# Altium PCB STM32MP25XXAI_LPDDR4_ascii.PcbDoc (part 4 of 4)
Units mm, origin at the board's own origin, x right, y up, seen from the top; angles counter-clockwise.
Board outline 172 x 137 mm, 4 copper layers (Top Layer, Signal Layer 1, Signal Layer 2, Bottom Layer), stack 1.614 mm thick; 188 components, 144 nets, 1216 pads, 838 vias.
Unrouted connection lines stored in the file: 13.
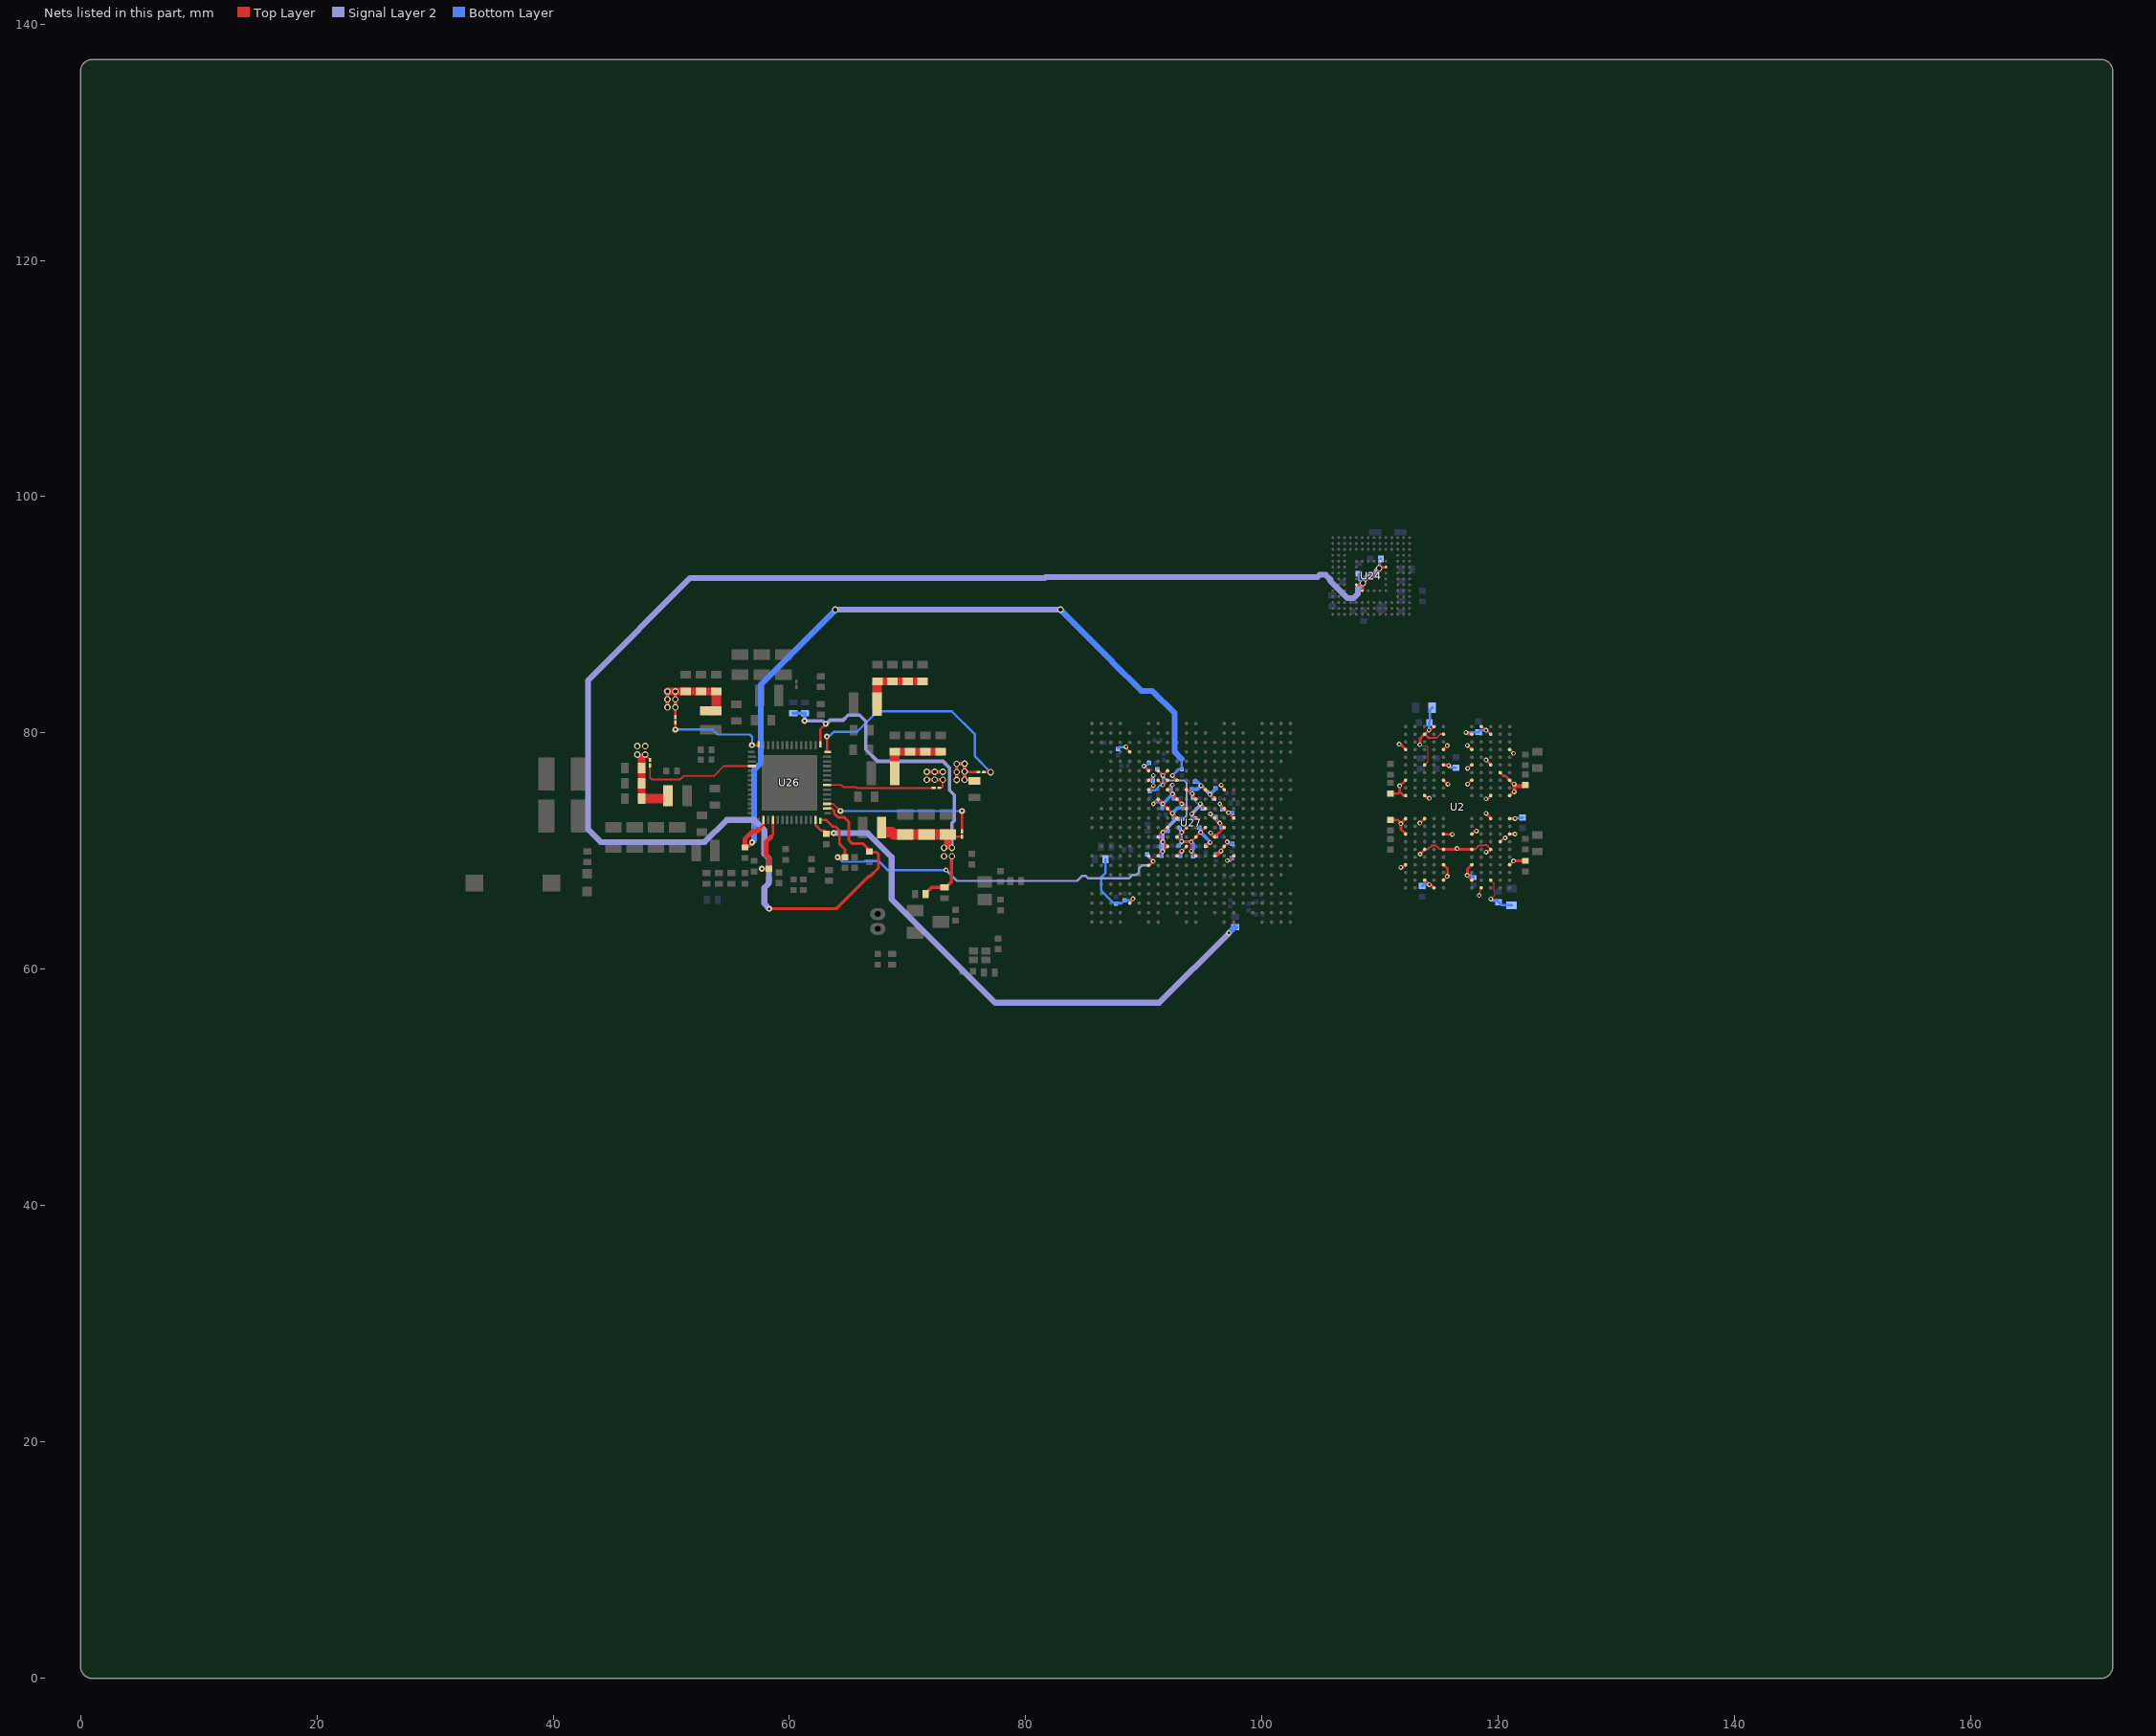
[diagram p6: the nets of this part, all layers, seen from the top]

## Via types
v1: diameter 0.55, hole 0.35, Top Layer to Bottom Layer, 387 vias
v2: diameter 0.4, hole 0.2, Top Layer to Bottom Layer, tented both sides, 173 vias
v3: diameter 0.5, hole 0.2, Top Layer to Bottom Layer, 146 vias
v4: diameter 0.4, hole 0.2, Top Layer to Bottom Layer, 129 vias
v5: diameter 0.5, hole 0.25, Top Layer to Bottom Layer, 3 vias

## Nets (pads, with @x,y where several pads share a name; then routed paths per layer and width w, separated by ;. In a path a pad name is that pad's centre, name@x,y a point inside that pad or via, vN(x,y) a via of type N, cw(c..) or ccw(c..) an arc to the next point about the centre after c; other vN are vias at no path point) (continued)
VDD2_DDR: C41.2 C50.1 C53.2 C54.1 C55.2 C56.2 C57.2 C58.2 C59.2 C60.2 C105.2 C106.1 C107.1 C108.1 C123.2 C124.1 C125.1 C130.1 C151.1 C175.1 C176.2 C200.2 C202.2 L5.2 LNK8.2 R163.2 U2.A4 U2.A9 U2.AA3 U2.AA5 U2.AA8 U2.AA10 U2.AB4 U2.AB9 U2.B3 U2.B5 U2.B8 U2.B10 U2.D1 U2.D5 U2.D8 U2.D12 U2.F3 U2.F5 U2.F8 U2.F10 U2.G2 U2.H1 U2.H5 U2.H8 U2.H12 U2.K1 U2.K3 U2.K10 U2.K12 U2.N1 U2.N3 U2.N10 U2.N12 U2.R1 U2.R5 U2.R8 U2.R12 U2.T2 U2.U3 U2.U5 U2.U8 U2.U10 U2.W1 U2.W5 U2.W8 U2.W12 U27.K15 U27.L14 U27.L16 U27.M15 U27.N14 U27.P15 U27.R14 U27.R16 | length 71.9
  Top Layer w0.09: v4(113.35,79) 113.413,78.938 113.905,78.938 114.045,78.797 114.045,77.595 U2.U10@113.75,77.3 ; v4(118.375,66.25) 118.397,66.271 118.397,66.524 118.515,66.642 118.515,66.865 U2.A4@118.55,66.9 ; v4(119.35,65.95) 119.695,66.295 119.695,66.593 119.645,66.643 119.645,67.255 U2.B3@119.35,67.55 ; U2.K3@119.35,72.775 U2.K3@119.35,72.788 ; U2.K1@120.95,72.825 U2.K1@120.975,72.825
  Top Layer w0.1: U27.R16@97.575,69.6 U27.R16@97.6,69.6
  Top Layer w0.15: v1(47.798,78.165) 48.2,77.763 LNK8.2@48.2,77.723 ; U2.F10@113.75,70.15 113.76,70.16 114.035,70.16 114.35,70.475 114.732,70.475 115.032,70.175 U2.F8@115.35,70.175 ; 114.095,79.575 114.75,79.575 115.075,79.9 U2.AA8@115.35,79.9 ; U2.F8@115.35,70.15 U2.F8@115.367,70.166 ; U2.F5@117.75,70.15 118.025,70.15 118.35,70.475 118.685,70.475 118.712,70.502 118.903,70.502 118.95,70.55 ; 118.95,70.525 118.975,70.525 119.325,70.175 U2.F3@119.375,70.175
  Top Layer w0.2: v2@95.6,73.15 v2(95.625,73.15) 95.65,73.15 U27.L14@96,72.8 v2(96.42,72.379) ; v2@95.625,71.575 U27.N14@96,71.2 U27.M15@96.8,72 v2@96.421,72.379 ; v2@96.4,74 U27.K15@96.8,73.6 v2(97.15,73.25) ; v2(96.525,70) 96.563,70.038 96.563,70.163 U27.P15@96.8,70.4 97.05,70.65 v2(97.05,70.8) ; v2(97.05,69.2) 97.2,69.2 U27.R16@97.6,69.6 ; v2@97.125,73.275 v2(97.15,73.25) ; U27.L16@97.6,72.8 v2(97.15,73.25)
  Top Layer w0.22: C50.1@110.85,72.65 111.46,72.65 111.735,72.375 v4@111.75,72.375 ; C105.2@110.85,74.875 111.502,74.875 111.651,75.024 ; v4(111.6,79.05) 111.635,79.016 111.735,79.016 U2.W12@112.15,78.6 ; v4(111.75,68.625) 111.785,68.659 111.938,68.659 112.129,68.85 U2.D12@112.15,68.85 ; U2.H12@112.15,71.45 111.755,71.845 111.755,72.37 v4@111.75,72.375 ; U2.K12@112.15,72.75 112.138,72.75 111.763,72.375 v4@111.75,72.375 ; U2.N12@112.15,74.7 112.135,74.715 111.96,74.715 111.651,75.024 ; U2.R12@112.15,76 112.15,75.988 111.65,75.488 111.65,75.475 111.651,75.474 111.651,75.024 ; v4(113.35,72.375) 113.363,72.375 113.738,72.75 U2.K10@113.75,72.75 ; v4(113.35,79) 113.38,79.03 113.38,79.53 U2.AA10@113.75,79.9 U2.AA10@113.77,79.9 ; v4(113.375,69.75) 113.75,70.125 U2.F10@113.75,70.15 ; U2.B10@113.75,67.55 113.763,67.55 114.138,67.175 v4(114.15,67.175) 114.185,67.141 114.288,67.141 114.529,66.9 U2.A9@114.55,66.9 ; U2.N10@113.75,74.7 113.772,74.7 113.953,74.519 114.116,74.519 v4@114.15,74.485 ; 114.095,79.575 U2.AA10@113.77,79.9 ; U2.AB9@114.55,80.55 114.538,80.55 114.188,80.2 114.175,80.2 114.141,80.166 114.038,80.166 113.772,79.9 U2.AA10@113.77,79.9 ; U2.B8@115.35,67.55 v4(115.675,67.875) 115.675,67.924 115.71,67.959 115.71,68.49 U2.D8@115.35,68.85 ; U2.F8@115.35,70.175 115.363,70.163 116.413,70.163 116.425,70.175 116.438,70.163 117.738,70.163 U2.F5@117.75,70.15 ; U2.H8@115.35,71.45 115.363,71.438 116.088,71.438 v4(116.1,71.425) ; U2.R8@115.35,76 115.372,76 115.697,75.675 v4(115.725,75.675) ; U2.U8@115.35,77.3 115.366,77.285 115.717,77.285 115.752,77.25 v4(115.8,77.25) ; U2.W8@115.35,78.6 v4(115.675,78.925) ; v4(117.25,80.05) 117.299,80.05 117.434,79.915 117.735,79.915 U2.AA5@117.75,79.9 ; v4(117.375,78.95) 117.388,78.95 117.738,78.6 U2.W5@117.75,78.6 ; v4(117.4,75.675) U2.R5@117.713,75.988 ; v4(117.4,77) 117.425,77 U2.U5@117.741,77.315 ; U2.B5@117.75,67.55 v4(117.35,67.95) 117.38,67.98 117.38,68.48 U2.D5@117.75,68.85 ; U2.H5@117.75,71.45 117.772,71.45 118.038,71.716 118.116,71.716 v4@118.15,71.75 ; U2.AB4@118.55,80.55 118.572,80.55 118.863,80.259 118.916,80.259 v4(118.95,80.225) 118.985,80.191 119.038,80.191 119.329,79.9 U2.AA3@119.35,79.9 ; v4(118.95,69.925) 118.985,69.959 119.138,69.959 119.329,70.15 U2.F3@119.35,70.15 ; v4(118.95,73.2) 118.95,73.172 119.35,72.772 U2.K3@119.35,72.75 ; v4(118.95,74.425) 118.985,74.459 119.11,74.459 U2.N3@119.35,74.7 ; v4(118.95,77.725) 118.95,77.713 119.35,77.313 U2.U3@119.35,77.3 ; U2.T2@120.123,76.655 120.145,76.655 U2.T2@120.15,76.65 120.425,76.375 120.575,76.375 U2.R1@120.95,76 121.241,75.709 121.316,75.709 v4(121.35,75.675) ; U2.G2@120.15,70.8 120.172,70.8 120.463,71.091 120.541,71.091 v4(120.575,71.125) ; U2.D1@120.95,68.85 v4(121.275,69.175) C106.1@122.25,69.175 ; U2.H1@120.95,71.45 v4(121.4,71.45) ; U2.K1@120.95,72.763 U2.K1@120.95,72.75 v4(121.4,72.75) ; U2.N1@120.95,74.7 121.241,74.991 121.316,74.991 v4(121.35,75.025) ; U2.W1@120.95,78.6 120.963,78.6 121.263,78.3 v4@121.275,78.3
  Top Layer w0.3: U27.R14@96,69.6 96.125,69.6 v2(96.525,70) ; v4(121.35,75.025) v4@121.35,75.495 ; v4(121.35,75.675) v4@121.35,75.495 ; C107.1@122.275,75.6 122.17,75.495 v4@121.35,75.495
  Top Layer w0.64: C202.2@47.475,74.45 C41.2@47.475,75.75 C200.2@47.475,77.05 ; 47.475,77.495 47.475,77.925
  Top Layer w0.8: C202.2@47.7,74.45 L5.2@49.475,74.45
  Signal Layer 2 w0.3: v2@96.356,72.394 96.406,72.394 v2@96.425,72.375
  Bottom Layer w0.2: v2@96.4,74 96.4,73.946 96.549,73.796 96.549,73.599 C60.2@96.624,73.524 ; C60.2@96.631,73.524 96.704,73.452 96.933,73.452 97.135,73.25 v2(97.15,73.25) ; v2@97.125,73.275 v2(97.15,73.25) ; v2@97.15,73.23 v2(97.15,73.25)
  Bottom Layer w0.22: v4(114.125,80.25) 114.125,80.825 114.202,80.901 114.202,81.926 C123.2@114.4,82.125 ; v4@114.125,80.275 114.125,80.85 C125.1@114.175,80.9 114.202,80.926 114.202,81.951 C123.2@114.4,82.15 ; v4@115.8,77.275 116.022,77.054 116.397,77.054 C130.1@116.4,77.05 ; v4(117.25,80.05) 118.275,80.05 C124.1@118.3,80.075 118.441,80.216 118.916,80.216 v4@118.95,80.25 ; v4@117.35,67.975 117.675,67.975 R163.2@117.9,67.75 ; v4@119.35,65.975 119.399,65.975 119.554,65.82 119.88,65.82 C108.1@120.025,65.675 120.05,65.675 120.3,65.425 C176.2@121.125,65.425 ; v4@121.4,72.775 121.435,72.809 122.01,72.809 C151.1@122.05,72.85
  Bottom Layer w0.275: C175.1@113.55,67.05 113.7,67.2 v4@114.15,67.2
  Bottom Layer w0.3: v2@95.6,71.575 95.9,71.275 C55.2@96.1,71.275 ; v2@95.6,73.15 v2(95.625,73.15) ; v2@95.627,73.15 v2(95.625,73.15) ; C59.2@96.1,69.725 96.175,69.8 96.308,69.8 96.508,70 v2(96.525,70) ; v2(96.42,72.379) 96.394,72.379 96.124,72.649 96.124,72.687 96.099,72.712 96.099,72.85 C56.2@96.074,72.875 96.049,72.9 95.875,72.9 v2(95.625,73.15) ; v2@96.425,72.375 96.425,72.347 96.549,72.223 96.549,71.999 C57.2@96.574,71.974 ; v2@97.023,70.8 v2(97.05,70.8) 97.077,70.8 97.227,70.65 97.45,70.65 C54.1@97.475,70.625 ; v2(97.05,69.2) 97.069,69.219 97.269,69.219 C53.2@97.45,69.4 ; v2@97.125,73.275 97.425,73.275 C58.2@97.5,73.2
  other v1: 47.123,78.165 47.123,78.89 47.798,78.89
  other v2: 95.65,71.55 96.425,74
  other v4: 116.5,70.225 118.15,71.7 111.75,72.325 114.15,74.475 111.65,75.525 121.275,78.275
VDD3V3_USB: C156.2 R286.1 U26.13 | length 47
  Top Layer w0.21: U26.13@62.2,72.63 62.2,72.2 62.663,71.737 62.918,71.737 62.92,71.735 62.99,71.735 63.125,71.6 C156.2@63.125,71.53
  Top Layer w0.3: C156.2@63.125,71.53 v3(63.735,71.53)
  Signal Layer 2 w0.5: v3(63.735,71.53) 66.62,71.53 68.65,69.5 68.65,65.93 77.411,57.17 91.295,57.17 97.19,63.065 v2(97.19,63.078)
  Bottom Layer w0.5: v2(97.19,63.078) 97.687,63.575 R286.1@97.725,63.575
VDD_DDR_FB: LNK8.1 U26.46 | length 10.2
  Top Layer w0.15: LNK8.1@48.2,77.273 48.2,76.19 48.317,76.073 50.767,76.073 51.067,76.373 51.737,76.373 51.739,76.375 53.627,76.375 54.452,77.2 U26.46@56.83,77.2
VDD_EMMC: C177.2 C180.2 C190.1 U24.E6 U24.F5 U24.J10 U24.K9 U26.16 | length 132.1
  Top Layer w0.2: U24.E6@107.98,92.542 108.285,92.542 108.435,92.692 v1(108.53,92.692) 108.53,92.1 108.48,92.05 U24.F5@108.48,92.042 ; v1(109.905,93.942) v1@109.98,94.017 ; U24.J10@109.98,94.542 109.98,94.112 109.972,94.104 109.972,94.025 v1@109.98,94.017 ; U24.K9@110.48,94.042 110.1,94.042 110.067,94.009 109.988,94.009 v1@109.98,94.017
  Top Layer w0.21: U26.16@63.17,73.6 63.6,73.6 63.788,73.412 63.788,73.188 63.934,73.041
  Top Layer w0.25: v3(58.3,65.125) 63.96,65.125 66.7,67.865 66.822,67.865 67.535,68.578 67.535,69.764 67.389,69.91 66.805,69.91 C190.1@66.75,69.965 ; 63.932,73.038 64.098,72.872 64.628,72.872 65.025,72.475 65.025,70.925 65.3,70.65 66.195,70.65 C190.1@66.75,70.095
  Top Layer w0.5: v1(108.53,92.692) v1@108.53,92.706 ; v1@109.895,93.919 v1@109.895,93.932
  Signal Layer 2 w0.5: v3(58.3,65.125) 57.872,65.553 57.872,66.908 58.265,67.301 58.265,69.369 57.872,69.762 57.872,71.786 57.009,72.649 54.703,72.649 52.827,70.773 44.024,70.773 42.958,71.839 42.958,84.457 51.616,93.115 81.606,93.115 81.691,93.2 104.684,93.2 104.871,93.387 105.389,93.387 105.755,93.021 105.755,92.873 107.221,91.407 107.739,91.407 108.105,91.773 108.105,92.254 108.53,92.679 v1(108.53,92.692) ; v1@108.605,92.946 108.986,93.327 109.374,93.327 109.755,93.708 109.755,93.779 v1@109.895,93.919
  Bottom Layer w0.2: C177.2@108.19,93.455 108.19,92.949 108.459,92.68 v1@108.55,92.68 ; v1@109.925,93.93 109.925,94.614 C180.2@110.05,94.739
VDD_SDCARD: C142.1 U26.4 | length 5.1
  Top Layer w0.21: 58.425,71.2 58.6,71.375 U26.4@58.6,72.63
  Top Layer w0.3: v3(57.665,68.51) C142.1@58.275,68.51
  Top Layer w0.4: C142.1@58.275,68.51 58.275,69.393 58.01,69.658 58.01,70.785 58.425,71.2
VDDA1V8_AON: C189.2 C234.2 U26.14 U27.R7 U27.T7 | length 35.8
  Top Layer w0.2: U27.T7@90.4,68.8 90.687,69.087 90.757,69.087 v2(90.795,69.125) 90.795,69.178 90.4,69.573 U27.R7@90.4,69.6
  Top Layer w0.21: U26.14@62.6,72.63 63.11,72.63 63.648,72.092 63.887,72.092 64.245,71.734 64.245,70.602 64.7,70.147 C189.2@64.7,69.49
  Top Layer w0.3: v3(64.09,69.49) C189.2@64.7,69.49
  Signal Layer 2 w0.2: v2(73.253,68.406) 73.259,68.406 74.183,67.482 84.342,67.482 84.76,67.9 85.091,67.9 85.292,67.699 88.734,67.699 89.034,68 89.2,68 89.366,68 89.6,68.234 89.6,68.566 89.835,68.8 90.47,68.8 v2(90.795,69.125) v2@90.726,69.125
  Bottom Layer w0.2: v3(64.09,69.49) 64.48,69.1 66.321,69.1 66.392,69.171 67.535,69.171 68.3,68.406 v2(73.253,68.406) ; C234.2@90.275,69.735 90.441,69.569 90.441,69.443 90.76,69.125 v2(90.795,69.125)
VDDCORE: C1.1 C2.2 C3.2 C4.1 C5.2 C6.2 C22.2 C23.2 C24.2 C66.2 C69.2 C70.2 C183.2 L2.2 LNK2.2 R249.1 U27.D5 U27.F7 U27.G7 U27.H7 U27.H9 U27.J8 U27.J10 U27.K9 U27.K11 U27.L10 | length 26.2
  Top Layer w0.2: C22.2@71.275,84.375 C22.2@71.323,84.423 ; v1@74.87,76.685 LNK2.2@75.98,76.685 ; v2(88.475,78.825) 88.475,78.725 U27.D5@88.8,78.4 ; v2(90,77.2) U27.F7@90.4,76.8 U27.F7@90.425,76.8 ; U27.H7@90.4,75.2 90.425,75.2 90.775,75.55 v2(90.8,75.55) ; U27.G7@90.4,76 v2(90.8,76.4) ; v2(90.8,74) U27.J8@91.2,74.4 v2(91.6,74) v2(92.4,73.2) U27.L10@92.8,72.8 ; v2(92.4,75.6) U27.H9@92,75.2 v2@92.425,74.775 ; v2(92.425,74.85) v2@92.425,74.775 ; U27.K11@93.6,73.6 v2(93.2,74) U27.J10@92.8,74.4 v2@92.425,74.775
  Top Layer w0.3: v1@74.151,77.404 v1(74.826,77.404) v1(74.826,76.729) ; v1(74.156,76.024) v1(74.156,76.699) v1(74.156,77.374) ; v1(74.826,76.054) v1(74.826,76.729) ; v1@74.87,76.685 v1(74.826,76.729)
  Top Layer w0.64: C183.2@67.45,84.375 C24.2@68.725,84.375 C23.2@70,84.375 C22.2@71.275,84.375
  Top Layer w0.8: L2.2@67.415,82.2 L2.2@67.415,82.45 C183.2@67.415,84.173
  Bottom Layer w0.2: C70.2@87.8,78.7 87.9,78.8 88.038,78.8 v2@88.4,78.8 ; v2(90,77.2) 90.038,77.238 90.188,77.238 C66.2@90.425,77.475 ; v2(90.8,75.55) 90.777,75.572 90.777,75.948 C69.2@90.755,75.97 90.777,75.992 90.777,76.378 v2(90.8,76.4)
  Bottom Layer w0.3: v2(90.8,74) 91,74.2 91.4,74.2 v2(91.6,74) ; C3.2@91.55,73.65 91.55,73.95 v2(91.6,74) ; v2(92.4,75.6) 92.275,75.475 C4.1@92.275,75.25 92.275,75 v2(92.425,74.85) ; C1.1@92.55,72.825 92.55,73.05 v2(92.4,73.2) 92.85,73.65 C2.2@93.326,73.65 93.325,73.875 v2(93.2,74) ; C5.2@92.551,74.475 92.55,74.725 v2(92.425,74.85) ; v2(91.6,74) 92.425,74.825 v2(92.425,74.85)
VDDCORE_FB: LNK2.1 U26.28 | length 19.9
  Top Layer w0.2: U26.28@63.17,78.4 v3(63.17,79.7) ; LNK2.1@76.444,76.687 v1@77.031,76.685
  Bottom Layer w0.2: v3(63.17,79.7) 63.227,79.757 63.401,79.757 63.754,80.111 65.734,80.111 67.457,81.833 73.744,81.833 75.675,79.902 75.675,78.041 v1(77.033,76.683)
VDDCPU: C13.1 C14.2 C15.2 C16.1 C17.2 C25.2 C26.2 C27.2 C28.2 C31.2 L3.2 LNK4.1 U27.H11 U27.H13 U27.H15 U27.J12 U27.J14 U27.K13 U27.L12 | length 21.1
  Top Layer w0.2: LNK4.1@50.35,81.35 v1(50.35,82.173) ; U27.H11@93.6,75.2 93.627,75.2 93.924,74.903 94.052,74.903 94.128,74.827 94.128,74.699 94.4,74.427 U27.J12@94.4,74.4 ; v2(94.045,73.155) U27.L12@94.4,72.8 ; v2(94.775,74.005) 95.18,73.6 U27.K13@95.2,73.6 ; v2(94.845,75.555) U27.H13@95.2,75.2 ; v2(95.595,74.805) U27.J14@96,74.4 ; v2(96.54,75.591) 96.578,75.553 96.578,75.449 96.8,75.227 U27.H15@96.8,75.2
  Top Layer w0.3: v1(49.675,82.173) v1(49.675,82.848) v1(49.675,83.523) v1(50.35,83.523) v1(50.35,82.848) v1(50.35,82.173)
  Top Layer w0.64: v1(49.675,83.523) 49.675,83.525 C27.2@51.2,83.525 C28.2@52.5,83.525 C26.2@53.8,83.525
  Top Layer w0.8: L3.2@53.35,81.875 53.8,81.875 53.8,83.173
  Signal Layer 2 w0.3: v2(94.045,73.155) 94.756,73.866 94.756,73.986 v2(94.775,74.005) ; v2(94.845,75.555) v2(95.595,74.805)
  Bottom Layer w0.1: C14.2@94.15,74.48 94.15,74.379 94.524,74.005 v2(94.775,74.005)
  Bottom Layer w0.2: v2(94.045,73.155) 94.045,72.855 C31.2@94.125,72.775 ; v2@94.775,73.978 v2(94.775,74.005) ; C13.1@94.95,73.625 94.95,73.803 ; v2(95.595,74.805) 95.633,74.767 95.633,74.692 C15.2@95.875,74.45
  Bottom Layer w0.3: v2(94.095,74.865) 94.095,74.892 94.05,74.937 94.05,75.225 C25.2@94.025,75.25 94.548,75.25 v2@94.853,75.555 ; C17.2@94.325,75.875 94.525,75.875 v2(94.845,75.555) ; v2@94.775,73.978 94.95,73.803 ; v2(95.595,74.805) C16.1@96.095,75.305
VDDCPU_FB: LNK4.2 U26.42 | length 8.6
  Top Layer w0.2: v3(50.35,80.29) LNK4.2@50.35,80.9 ; v3(56.825,78.975) U26.42@57.395,78.975
  Bottom Layer w0.2: v3@50.37,80.287 53.499,80.287 53.914,79.872 56.643,79.872 56.845,79.67 v3@56.845,78.972
VDDGPU: C7.2 C8.2 C9.2 C10.2 C11.1 C12.2 C34.2 C35.2 C36.2 C37.2 L4.2 LNK7.2 U27.M11 U27.M13 U27.N10 U27.N12 U27.P13 U27.R12 | length 21.3
  Top Layer w0.15: LNK7.2@72.675,75.35 72.682,75.358 72.885,75.358 72.973,75.445 v1(72.973,76.038)
  Top Layer w0.2: C35.2@73.05,78.393 C35.2@73.098,78.345 ; U27.M11@93.6,72 v2(93.2,71.6) U27.N10@92.8,71.2 93.197,70.803 93.997,70.803 v2(94,70.8) ; U27.R12@94.4,69.6 v2(94,70) v2(94,70.8) ; U27.P13@95.2,70.4 95.487,70.687 95.562,70.687 v2(95.6,70.725) ; U27.M13@95.2,72 v2(94.8,71.6) v2(94,70.8)
  Top Layer w0.3: v1(71.623,76.038) v1(72.298,76.038) v1(72.973,76.038) ; v1(71.623,76.713) v1(72.298,76.713) v1(72.973,76.713)
  Top Layer w0.64: C37.2@68.9,78.4 C36.2@70.2,78.4 C34.2@71.5,78.4 C35.2@72.8,78.4
  Top Layer w0.8: L4.2@68.925,76.6 68.925,78.073
  Bottom Layer w0.2: C9.2@93.025,72 93.025,71.775 v2(93.2,71.6) 93.197,71.598 93.197,70.808 93.195,70.805 93.197,70.803 93.997,70.803 v2(94,70.8) ; v2(95.6,70.725) v2@95.61,70.715
  Bottom Layer w0.3: C10.2@92.95,70.48 93.176,70.706 93.176,70.786 v2@93.195,70.805 ; v2(94,70.8) 94.175,70.625 94.175,70.175 v2(94,70) 94.2,69.8 C12.2@94.2,69.575 ; C7.2@94.675,72 94.8,71.875 v2(94.8,71.6) 94.833,71.567 95.581,70.819 95.581,70.744 v2(95.6,70.725) 95.581,70.706 95.506,70.706 C11.1@95.25,70.45
  other v2: 93.2,70.805
VDDGPU_FB: LNK7.1 U26.21 | length 9.3
  Top Layer w0.15: U26.21@63.05,75.6 64.383,75.6 64.56,75.423 65.64,75.423 65.713,75.35 LNK7.1@72.225,75.35
VDDIO: C19.2 C44.1 C45.2 C46.2 C47.1 C52.2 C73.2 C74.2 C186.2 C187.2 L6.2 LNK11.2 R27.2 R67.2 R260.2 R261.2 U26.29 U27.F8 U27.F9 U27.G8 U27.G9 U27.M9 U27.N8 U27.P9 U27.P11 U27.R8 U27.R10 | length 61.4
  Top Layer w0.2: U26.29@62.6,79.045 62.6,80.298 v3(63.075,80.773) ; C186.2@73.4,71.4 73.585,71.215 LNK11.2@74.6,71.215 ; U27.R8@91.2,69.6 v2(91.575,69.975) U27.P9@92,70.4 v2(91.6,70.8) U27.N8@91.2,71.2 v2(91.6,71.6) U27.M9@92,72 ; U27.G8@91.2,76 91.599,75.6 U27.G9@92,76 ; U27.F8@91.2,76.8 v2(91.6,76.4) U27.F9@92,76.8 ; U27.R10@92.8,69.6 v2(93.2,70) U27.P11@93.6,70.4
  Top Layer w0.3: R67.2@71.525,66.375 71.525,66.44 72.01,66.925 R27.2@73.125,66.925 73.23,67.03 73.339,67.03 73.712,67.402 73.712,69.52 v1(73.752,69.56) ; v1(73.077,69.56) v1@73.125,69.512
  Top Layer w0.64: 73.4,70.525 C186.2@73.4,70.955
  Top Layer w0.9: L6.2@67.85,71.6 68.65,71.6 68.85,71.4 C187.2@69.8,71.4 C19.2@71.6,71.4 C186.2@73.4,71.4
  Signal Layer 2 w0.15: v2(91.599,75.599) 91.971,75.971 91.962,75.98 ; v2@91.6,76.338 v2@91.6,76.342 ; v2(91.6,76.4) v2@91.6,76.342 ; 93.301,72.703 93.608,73.01 93.608,75.783 93.411,75.98 91.962,75.98 ; v2@91.6,76.342 91.962,75.98
  Signal Layer 2 w0.3: v3(61.284,81.027) 62.799,81.027 63.05,80.776 v3@63.075,80.776 ; v3(63.075,80.773) 63.129,80.773 63.44,81.084 64.543,81.084 64.973,81.513 65.931,81.513 66.455,80.989 66.455,78.601 67.456,77.6 72.999,77.6 73.551,77.048 73.551,75.156 73.951,74.756 73.951,72.573 73.752,72.375 v1(73.752,70.285) ; v2(91.575,69.975) 91.6,70 v2(91.6,71.6) 92.703,72.703 93.301,72.703
  Bottom Layer w0.2: C74.2@90.5,75.05 90.575,75.125 90.667,75.125 90.692,75.15 90.931,75.15 90.946,75.165 90.981,75.165 91.2,75.384 91.2,75.419 91.342,75.561 91.561,75.561 v2(91.599,75.599) 91.6,76.4 91.6,76.45 C73.2@91.125,76.925
  Bottom Layer w0.3: R260.2@60.33,81.68 R261.2@61.305,81.68 61.294,81.669 61.294,81.038 v3(61.284,81.027) ; C44.1@91.475,69.6 91.475,69.875 v2(91.575,69.975) 91.475,70.075 91.475,70.675 v2(91.6,70.8) 91.475,70.925 91.475,71.475 91.725,71.725 C46.2@92.025,71.725 ; C45.2@93.075,69.6 93.075,69.875 v2(93.2,70) v2@93.225,70
  other v1: 73.077,70.285
VDDIO_FB: LNK11.1 U26.17 | length 13.4
  Top Layer w0.15: U26.17@63.17,74 63.7,74 64.303,73.397 v3(64.315,73.397)
  Top Layer w0.2: LNK11.1@74.6,71.665 v3(74.6,73.4)
  Bottom Layer w0.15: v3(64.315,73.397) v3@74.597,73.397
VDDIO_SDCARD: C71.2 C217.1 U26.2 U27.G10 | length 65.5
  Top Layer w0.2: v2(92.4,76.4) U27.G10@92.8,76
  Top Layer w0.21: 57.459,71.873 57.8,72.214 U26.2@57.8,72.63
  Top Layer w0.3: C217.1@56.225,70.38 56.27,70.425 56.559,70.425 56.835,70.701 v3(56.835,70.737)
  Top Layer w0.4: C217.1@56.225,70.32 56.225,70.38 56.225,71.015 56.899,71.69 57.275,71.69 57.459,71.873
  Signal Layer 2 w0.5: v1(63.865,90.43) 63.867,90.432 82.942,90.432 v1(82.945,90.435)
  Bottom Layer w0.2: v2(92.4,76.4) 92.95,76.95 C71.2@93.201,76.95 93.201,77.799
  Bottom Layer w0.5: v3(56.835,70.737) 57.009,70.911 57.009,76.91 57.581,77.482 57.581,81.596 57.575,81.601 57.575,82.099 57.581,82.104 57.581,84.092 63.855,90.367 63.855,90.42 v1(63.865,90.43) ; v1@82.945,90.444 v1(82.945,90.435) 87.294,86.086 87.294,86.055 89.779,83.57 90.696,83.57 92.605,81.661 92.605,78.395 93.2,77.8
VREF+: C67.2 C68.2 R269.2 U27.Y5 | length 6.6
  Top Layer w0.2: U27.Y5@88.8,65.6 89.037,65.837 89.037,65.942 v2(89.076,65.981)
  Bottom Layer w0.2: R269.2@86.754,69.315 86.754,68.159 86.402,67.808 86.402,66.63 87.387,65.645 87.585,65.645 87.63,65.6 88.125,65.6 C68.2@88.375,65.85 88.904,65.85 89.035,65.981 v2(89.076,65.981)
pads on no net: U2.A1 U2.A2 U2.A8 U2.A11 U2.A12 U2.AA1 U2.AA12 U2.AB1 U2.AB2 U2.AB11 U2.AB12 U2.B1 U2.B12 U2.G11 U2.H3 U2.J5 U2.K5 U2.K8 U2.N5 U2.N8 U2.P5 U2.R3 U24.A1 U24.A2 U24.A7 U24.A8 U24.A9 U24.A10 U24.A11 U24.A12 U24.A13 U24.A14 U24.B1 U24.B7 U24.B8 U24.B9 U24.B10 U24.B11 U24.B12 U24.B13 U24.B14 U24.C1 U24.C3 U24.C5 U24.C7 U24.C8 U24.C9 U24.C10 U24.C11 U24.C12 U24.C13 U24.C14 U24.D1 U24.D2 U24.D3 U24.D4 U24.D12 U24.D13 U24.D14 U24.E1 U24.E2 U24.E3 U24.E5 U24.E8 U24.E9 U24.E10 U24.E12 U24.E13 U24.E14 U24.F1 U24.F2 U24.F3 U24.F10 U24.F12 U24.F13 U24.F14 U24.G1 U24.G2 U24.G3 U24.G10 U24.G12 U24.G13 U24.G14 U24.H1 U24.H2 U24.H3 U24.H12 U24.H13 U24.H14 U24.J1 U24.J2 U24.J3 U24.J12 U24.J13 U24.J14 U24.K1 U24.K2 U24.K3 U24.K6 U24.K7 U24.K10 U24.K12 U24.K13 U24.K14 U24.L1 U24.L2 U24.L3 U24.L12 U24.L13 U24.L14 U24.M1 U24.M2 U24.M3 U24.M7 U24.M8 U24.M9 U24.M10 U24.M11 U24.M12 U24.M13 U24.M14 U24.N1 U24.N3 U24.N6 U24.N7 U24.N8 U24.N9 U24.N10 U24.N11 U24.N12 U24.N13 U24.N14 U24.P1 U24.P2 U24.P7 U24.P8 U24.P9 U24.P10 U24.P11 U24.P12 U24.P13 U24.P14 U27.A2 U27.A3 U27.A4 U27.A7 U27.A8 U27.A11 U27.A12 U27.A15 U27.A16 U27.A21 U27.AA1 U27.AA2 U27.AA3 U27.AA4 U27.AA6 U27.AA7 U27.AA8 U27.AA10 U27.AA11 U27.AA12 U27.AA14 U27.AA15 U27.AA16 U27.AA18 U27.AA19 U27.AA20 U27.AA21 U27.AB2 U27.AB3 U27.AB4 U27.AB7 U27.AB8 U27.AB11 U27.AB12 U27.AB15 U27.AB16 U27.AB19 U27.AB20 U27.AB21 U27.B1 U27.B2 U27.B3 U27.B4 U27.B5 U27.B7 U27.B8 U27.B9 U27.B11 U27.B12 U27.B13 U27.B15 U27.B16 U27.B17 U27.B20 U27.B21 U27.C1 U27.C2 U27.C3 U27.C5 U27.C6 U27.C8 U27.C9 U27.C10 U27.C11 U27.C12 U27.C13 U27.C14 U27.C15 U27.C16 U27.C17 U27.C20 U27.D1 U27.D2 U27.D3 U27.D4 U27.D6 U27.D7 U27.D8 U27.D9 U27.D10 U27.D11 U27.D12 U27.D13 U27.D14 U27.D15 U27.D16 U27.D19 U27.E3 U27.E4 U27.E6 U27.E7 U27.E8 U27.E9 U27.E10 U27.E11 U27.E12 U27.E13 U27.E14 U27.E15 U27.E18 U27.F2 U27.F3 U27.F4 U27.F5 U27.F11 U27.F12 U27.F13 U27.F14 U27.F15 U27.G1 U27.G2 U27.G3 U27.G4 U27.G5 U27.G11 U27.G12 U27.G13 U27.G14 U27.G16 U27.H1 U27.H2 U27.H3 U27.H4 U27.H5 U27.H6 U27.J3 U27.J4 U27.J5 U27.J6 U27.J7 U27.K2 U27.K3 U27.K4 U27.K5 U27.K6 U27.K7 U27.K17 U27.K18 U27.L1 U27.L2 U27.L3 U27.L4 U27.L5 U27.L6 U27.L7 U27.L20 U27.M1 U27.M2 U27.M3 U27.M4 U27.M5 U27.M6 U27.M18 U27.N3 U27.N4 U27.N5 U27.N6 U27.P2 U27.P3 U27.P4 U27.P5 U27.P16 U27.P17 U27.R3 U27.R4 U27.R5 U27.R6 U27.R17 U27.R18 U27.R19 U27.T1 U27.T2 U27.T8 U27.T9 U27.T10 U27.T11 U27.T12 U27.T13 U27.T14 U27.T15 U27.T17 U27.T19 U27.U4 U27.U5 U27.U8 U27.U9 U27.U10 U27.U11 U27.U12 U27.U13 U27.U14 U27.U15 U27.U16 U27.U18 U27.U19 U27.V4 U27.V5 U27.V6 U27.V8 U27.V9 U27.V10 U27.V11 U27.V12 U27.V13 U27.V14 U27.V15 U27.V16 U27.V17 U27.W1 U27.W2 U27.W3 U27.W4 U27.W6 U27.W7 U27.W9 U27.W10 U27.W11 U27.W12 U27.W13 U27.W14 U27.W15 U27.W17 U27.Y1 U27.Y3 U27.Y4 U27.Y6 U27.Y7 U27.Y8 U27.Y9 U27.Y10 U27.Y11 U27.Y12 U27.Y13 U27.Y14 U27.Y15 U27.Y17 U27.Y18 U27.Y20
copper on no net: | length 328.5
  Top Layer w0.09: 81.172,76.702 85.898,76.702 86.105,76.495 88.305,76.495 88.8,76 ; 81.614,76.882 86.261,76.882 86.343,76.8 86.4,76.8 ; 81.76,77.09 86.513,77.09 86.803,76.8 87.2,76.8 ; 82.23,77.27 86.59,77.27 86.775,77.085 87.332,77.085 87.342,77.075 87.575,76.842 87.59,76.827 87.973,76.827 88,76.8 ; 82.334,77.52 86.693,77.52 86.898,77.315 87.427,77.315 87.437,77.305 87.657,77.085 88.515,77.085 88.8,76.8 ; 82.986,77.7 87.043,77.7 87.143,77.6 87.2,77.6 ; 83.083,77.935 87.665,77.935 88,77.6 ; 83.395,70.522 83.453,70.522 83.53,70.445 85.911,70.445 86.233,70.123 86.549,70.123 86.777,69.895 87.556,69.895 87.76,70.099 ; 83.448,70.265 85.754,70.265 86.124,69.895 86.522,69.895 86.817,69.6 87.2,69.6 ; 83.537,70.707 83.619,70.625 86.175,70.625 86.4,70.4 ; 83.604,70.895 83.694,70.805 86.412,70.805 86.695,70.522 86.695,70.28 86.9,70.075 87.406,70.075 87.731,70.4 88,70.4 ; 83.673,71.08 83.758,70.995 86.477,70.995 87.032,70.44 87.16,70.44 87.2,70.4 ; 83.685,78.115 85.718,78.115 86.003,78.4 86.4,78.4 ; 83.748,71.26 83.833,71.175 86.551,71.175 87.031,70.695 88.295,70.695 88.8,71.2 ; 83.789,78.365 85.565,78.365 85.6,78.4 ; 83.877,71.64 83.982,71.535 86.75,71.535 87.045,71.24 87.16,71.24 87.2,71.2 ; 84.075,71.875 84.235,71.715 86.827,71.715 87.047,71.495 88.295,71.495 88.8,72 ; 84.174,72.075 84.249,72 ; 84.615,68.995 85.224,68.995 85.354,69.125 87.525,69.125 88,69.6 ; 84.65,68.41 85.613,68.41 86.003,68.8 86.4,68.8 ; 84.862,74.565 86.439,74.565 86.939,75.065 87.011,75.065 87.146,75.2 87.2,75.2 ; 85.472,78.675 85.482,78.685 86.603,78.685 86.875,78.413 86.875,78.3 87.06,78.115 87.715,78.115 88,78.4 ; 85.472,78.925 85.482,78.915 86.642,78.915 87.157,78.4 87.2,78.4 ; 86.115,75.475 86.125,75.475 86.4,75.2 ; 86.865,75.665 87.2,76 ; 87.359,70.885 87.361,70.885 87.683,70.885 87.998,71.2 ; 87.424,60.877 89.925,63.377 89.925,64.197 90.105,64.377 90.105,65.305 90.4,65.6 ; 87.634,82.95 89.145,81.439 89.145,80.673 89.52,80.298 89.52,79.693 89.885,79.328 89.885,78.115 90.4,77.6 ; 87.634,60.832 90.105,63.303 90.105,64.122 90.4,64.417 90.4,64.8 ; 87.738,83.2 89.395,81.543 89.395,81.439 89.395,80.91 89.394,80.909 89.394,80.776 89.75,80.42 89.75,79.788 90.115,79.424 90.115,78.273 90.273,78.115 90.347,78.115 90.4,78.168 90.4,78.4 ; 87.796,81.5 88.106,81.19 88.285,81.011 88.285,79.715 88.8,79.2 ; 87.826,82.15 88.715,81.261 88.715,80.495 89.085,80.125 89.085,78.915 89.6,78.4 ; 87.87,60.813 90.4,63.343 90.4,64 ; 87.9,81.75 88.535,81.115 88.535,81.011 88.535,79.853 88.673,79.715 88.747,79.715 88.8,79.768 88.8,80 ; 87.93,82.4 88.965,81.365 88.965,80.599 89.335,80.229 89.335,79.053 89.473,78.915 89.547,78.915 89.6,78.968 89.6,79.2 ; 88.124,70.099 88.405,70.38 88.78,70.38 88.8,70.4 ; 89.745,63.452 89.745,64.271 89.925,64.451 89.925,65.925 90.4,66.4 ; v2@90.8,78 91.2,77.6 ; v2(90.846,66.845) 91.2,67.2 ; v2(90.846,67.645) 91.2,68 ; v2@90.865,65.226 v2(90.846,65.245) 91.2,65.6 ; v2(91.525,66.825) 91.575,66.825 91.95,67.2 92,67.2 ; 92.145,63.204 92.145,65.071 92.505,65.431 92.505,65.722 92.505,66.905 92.8,67.2 ; 92.325,62.976 92.325,64.997 92.603,65.275 92.744,65.275 92.8,65.331 92.8,65.6 ; 92.505,62.82 92.505,64.922 92.678,65.095 92.969,65.095 93.12,65.247 93.12,66.08 92.8,66.4 ; 92.765,62.66 92.765,64.346 92.825,64.406 92.825,64.775 92.8,64.8 ; v2(93.05,66.775) 93.294,67.019 93.364,67.019 93.545,67.2 93.6,67.2 ; 93.29,82.424 93.29,80.31 93.6,80 ; 93.6,76 v2@94,76.4 ; v2(93.898,66.003) 93.93,66.035 93.93,66.75 94.38,67.2 94.4,67.2 ; 93.925,62.425 93.925,65.173 94.105,65.353 94.105,65.722 94.25,65.868 94.25,66.239 94.4,66.389 94.4,66.4 ; v2(93.95,67.6) 94.35,68 94.4,68 ; 94.105,62.105 94.105,64.122 94.4,64.417 94.4,64.8 ; 94.4,61.975 94.4,64 ; 94.4,65.6 94.695,65.305 94.695,61.851 ; 95.045,81.28 95.045,80.533 94.915,80.403 94.915,79.882 95.2,79.597 95.2,79.2 ; 95.2,67.2 95.541,67.541 95.541,67.734 v2(95.6,67.793) ; 95.275,61.5 95.275,65 95.495,65.22 95.495,66.775 95.495,67.2 95.858,67.563 96.163,67.563 96.4,67.8 96.4,68.048 96,68.448 96,68.8 ; 95.455,61.383 95.455,64.913 95.675,65.133 95.675,66.875 96,67.2 ; 95.585,81.665 95.585,80.308 95.69,80.203 95.69,78.71 96,78.4 ; 95.635,61.266 95.635,64.838 96,65.203 96,65.6 ; 95.765,81.835 95.765,80.383 95.87,80.278 95.87,79.361 96,79.231 96,79.2 ; 95.833,61.167 95.833,64.576 96,64.743 96,64.8 ; 95.945,81.98 95.945,80.457 96.05,80.352 96.05,79.588 96.31,79.328 96.31,77.91 96,77.6 ; 96,66.4 96.295,66.105 96.295,64.62 96.081,64.406 96.081,61.118 ; 96,68 96,68.025 ; 96.125,82.2 96.125,80.532 96.23,80.427 96.23,79.663 96.49,79.403 96.49,78.8 96.49,78.71 96.8,78.4 ; 96.305,82.495 96.305,80.606 96.41,80.501 96.41,79.866 96.781,79.495 96.781,79.219 96.8,79.2 ; 96.315,60.815 96.315,64.385 96.475,64.545 96.475,66.875 96.8,67.2 ; 96.485,82.74 96.485,80.681 96.59,80.576 96.59,80.225 96.8,80.015 96.8,80 ; 99.2,64.8 99.166,64.834 98.961,64.834 98.875,64.749 98.875,63.825 99.3,63.4 99.3,61.425 99.525,61.2 ; 99.2,65.6 99.192,65.592 99.192,65.381 99.035,65.224 98.997,65.224 98.625,64.852 98.625,63.721 99.05,63.296 99.05,61.321 99.275,61.096 ; 100,64 99.96,64.04 99.96,64.219 99.904,64.275 99.756,64.275 99.7,64.219 99.7,63.8 99.775,63.725 100.025,63.475 100.025,61.9 100.548,61.378 100.799,61.126 ; 100,64.8 99.96,64.76 99.96,64.581 99.904,64.525 99.622,64.525 99.45,64.354 99.45,63.696 99.775,63.371 99.775,61.796 100.361,61.211 100.549,61.022 ; 100.525,62.771 100.525,63.446 100.285,63.687 100.285,64.106 100.76,64.581 100.76,64.76 ; 100.76,64.04 100.709,63.989 100.588,63.989 100.535,63.937 100.535,63.79 100.775,63.55 100.775,62.875 ; 101.6,64 101.56,64.04 101.56,64.195 101.504,64.251 101.425,64.251 101.335,64.16 101.335,63.85 101.445,63.74 101.445,63.509 102,62.954 102.85,62.104 103.082,61.872 ; 101.6,64.8 101.56,64.76 101.56,64.585 101.5,64.525 101.346,64.525 101.085,64.264 101.085,63.746 101.195,63.637 101.195,63.543 101.195,63.406 101.75,62.85 102.6,62 102.832,61.768
  Top Layer w0.1: 81.172,76.29 85.72,76.29 86.01,76 86.4,76 ; 83.388,70.325 83.448,70.265 ; 83.838,62.335 84.635,63.132 84.635,63.791 85.244,64.4 86,64.4 86.4,64.8 ; 84.249,72 85.6,72 ; 84.29,68.41 84.65,68.41 ; 84.378,68.994 84.614,68.994 84.615,68.995 ; 84.412,68.8 85.6,68.8 ; 85.063,65.025 85.063,65.473 85.48,65.89 85.89,65.89 86.4,66.4 ; 85.199,73.085 85.394,73.28 85.792,73.28 86.162,72.91 86.236,72.91 86.346,72.8 86.4,72.8 ; 85.38,75.659 85.401,75.68 86.126,75.68 86.141,75.665 86.865,75.665 ; 85.459,75.469 85.48,75.49 85.79,75.49 85.805,75.475 86.115,75.475 ; v2(87.6,73.2) 88,73.6 ; 87.76,70.099 88.124,70.099 ; 87.914,74.011 89.989,74.011 90.4,73.6 ; 88,67.2 88,66.81 88.49,66.32 88.49,63.265 ; v2(88.4,72.4) 88.8,72.8 ; v2(88.4,73.2) 88.8,73.6 ; v2(88.4,74.8) 88.8,74.4 ; v2(88.4,75.6) 88.8,75.2 ; 88.722,63.227 88.722,64.601 89.31,65.189 89.31,65.72 89.6,66.01 89.6,66.4 ; 88.912,63.149 88.912,64.522 89.6,65.21 89.6,65.6 ; 89.102,63.07 89.102,64.302 89.6,64.8 ; v2(89.2,71.6) 89.6,72 ; v2(89.2,72.4) 89.6,72.8 ; v2(89.2,73.2) 89.6,73.6 ; v2(89.2,74.8) 89.6,74.4 ; v2(89.2,75.6) 89.6,75.2 ; v2(89.2,78) 89.6,77.6 ; v2(90.8,68.4) 91.2,68.8 ; v2(91.6,67.6) 92,68 ; v2(91.6,68.4) 92,68.8 ; v2(92.4,67.6) 92.8,68 ; v2(92.4,68.4) 92.8,68.8 ; 92.8,78.4 v2@93.2,78.8 ; v2(93.2,67.6) 93.6,68 ; v2(93.2,68.4) 93.6,68.8 ; v2(94,68.4) 94.4,68.8 ; 94.4,76.8 v2@94.8,77.2 ; v2(94.8,76.4) 95.2,76 ; v2(95.6,68.4) 96,68 ; 97.536,63.661 97.603,63.728 97.603,63.997 97.6,64 ; 97.6,64.8 97.6,64.439 97.89,64.149 97.89,63.88 97.823,63.813 97.823,63.637 97.756,63.569 ; 97.6,67.2 v2(98,66.8) ; 98.35,61.975 98.08,62.245 98.08,64.88 98.48,65.28 98.48,65.466 98.4,65.546 98.4,65.6 ; 98.4,66.4 98.4,66.01 98.7,65.71 98.7,65.189 98.3,64.789 98.3,62.336 98.57,62.066 ; 98.4,67.2 98.643,66.957 98.643,66.857 v2(98.7,66.8)
  Top Layer w0.11: v2(94.65,66) 94.606,66 94.662,66.055 94.855,66.055 95.2,66.4 ; v2(94.8,66.8) 94.8,67.602 95.198,68 95.2,68 ; v2(94.8,69.075) 95.2,68.8 ; 96.8,80.8 96.8,82.85
  Top Layer w0.2: 88.8,67.2 88.827,67.2 89.103,66.924 89.226,66.924 v2(89.264,66.886) ; v2(90.01,73.23) 90.01,73.21 90.4,72.82 90.4,72.8
  Bottom Layer w0.11: v2@94.8,66.752 v2(94.8,66.8) ; v2@95.6,67.709 v2(95.6,67.793)
  Bottom Layer w0.2: v2@89.264,66.858 v2(89.264,66.886)
  other v2: 94,76.4 94.8,77.2 90.8,78 93.2,78.8 87.6,80.42

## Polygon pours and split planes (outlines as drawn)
GND on Bottom Layer "GND_L04" (solid, pour order 154): 0.225,137.075 172,137.075 172,-0.225 0.025,-0.225
5V_STLK on Bottom Layer "5V_STLK_L04" (solid, pour order 149): 42.715,94.735 42.76,94.78 72.14,94.78 72.14,59.34 72.155,59.325 42.73,59.325
1V8 on Bottom Layer "1V8_L04" (solid, pour order 0): 84.939,76.533 84.939,85.255 86.38,85.255 86.38,82.845 86.37,82.843 92.23,82.843 92.23,77.2 90.71,77.2 90.71,81.299 87.934,81.299 87.934,79.63 87.966,79.598 89.365,79.159 89.365,76.533
GND on Signal Layer 2 "GND_L03" (solid, remove dead copper, pour order 152): 0,137 172,137 172,0 0,0
VDD2_DDR on Signal Layer 2 "VDD2_DDR" (solid, remove dead copper, pour order 144): 97.557,75.295 95.405,73.143 95.405,71.413 95.543,71.275 96.075,71.275 96.075,71.26 96.33,71.006 96.33,69.119 96.572,68.877 97.557,68.877 98.8,67.634 98.8,67.25 100.575,65.475 121.35,65.475 121.35,80.473 105.891,80.534 96.44,89.985 50.853,89.985 46.246,85.378 46.246,78.14 46.918,77.468 48.216,77.468 49.219,78.471 49.219,83.775 49.539,84.095 93.76,84.095 95.32,82.536 97.557,80.298
1V8 on Signal Layer 2 "1V8" (solid, pour order 151): 60.675,96.6 60.675,93.472 105.856,93.472 105.904,85.175 117.725,85.175 117.725,96.6
VDDGPU on Signal Layer 2 "VDDGPU" (solid, remove dead copper, pour order 127): 95.348,72.122 95.348,71.47 95.61,71.208 98.541,68.277 98.541,64.841 91.09,57.39 77.655,57.39 69.27,65.607 69.27,70.917 66.599,73.523 66.599,75.759 68.13,77.29 73.63,77.29 73.63,72.863 72.549,71.782 72.549,69.54 74.374,67.715 89.374,67.715 91.607,69.923 93.267,69.923 93.441,70.097 93.441,70.49 92.994,71.003 92.994,72.331 95.14,72.331
5V_STLK on Signal Layer 2 "5V_STLK_L03" (solid, pour order 150): 43.375,82.635 68.935,82.635 68.975,82.595 68.975,66.229 43.411,66.229
3V3 on Signal Layer 2 "3V3_L03" (solid, remove dead copper, pour order 146): 58,61.394 57.939,61.394 37.983,61.394 35.711,61.394 35.711,67.822 35.711,84.011 44.436,84.011 44.436,73.55 45.447,72.539 58,72.539
VDDIO on Signal Layer 2 "VDDIO_L03" (solid, remove dead copper, pour order 145): 93.852,70.39 93.235,69.772 91.585,69.772 89.378,67.564 74.378,67.564 72.553,69.389 72.553,71.646 73.945,73.038 93.024,73.038 93.852,72.21
VDDCORE on Signal Layer 2 "VDDCORE" (solid, remove dead copper, pour order 142): 93.118,75.605 93.118,77.055 91.173,79 73.745,79 73.745,73.019 93.843,73.019 93.843,74.83
VDDCPU on Signal Layer 2 "VDDCPU" (solid, remove dead copper, pour order 143): 97.516,75.448 94.844,72.776 94.833,72.775 92.631,72.775 92.631,76.645 92.631,77.532 91.618,78.545 66.455,78.545 66.455,80.62 66.505,80.67 66.175,81 60.143,81 60.055,80.912 59.116,81.85 49.319,81.85 49.219,81.75 49.219,83.775 50.843,85.4 59.717,85.4 60.603,84.513 60.603,84.5 93.355,84.5 97.516,80.339 97.516,76.697
GND on Top Layer "GND_L01" (solid, pour order 153): 0.178,137.102 0.303,136.977 172,136.977 172,-0.323 0.103,-0.323
3V3 on Top Layer "3V3" (solid, pour order 137): 44.387,68.548 44.562,68.373 50.91,68.373 52.212,69.675 52.212,70.523 44.588,70.523 44.387,70.323
5V_STLK on Top Layer "5V_STK" (solid, pour order 111): 54.01,75.62 54.667,75.62 54.85,75.803 54.85,75.463 54.367,74.98 54.01,74.98
VDDCPU on Top Layer "I_SENS_VDDCPU_P" (solid, pour order 133): 49.312,83.845 49.312,81.998 49.835,81.475 54.25,81.475 54.245,81.48 54.245,83.845
VDDCORE on Top Layer "I_SENS_VDDCORE_P" (solid, pour order 134): 72.507,84.74 75.389,81.858 75.389,75.631 75.394,75.626 73.94,75.626 73.395,76.171 73.395,80.872 73.022,81.245 71.375,81.245 67.015,81.245 67.005,84.74
VDDGPU on Top Layer "I_SENS_VDDGPU_P" (solid, pour order 135): 73.103,75.6 73.245,75.742 73.245,78.72 68.525,78.72 68.525,75.6
VDDIO on Top Layer "VDDIO" (solid, pour order 136): 62.495,78.77 62.495,80.568 63.03,81.103 63.212,81.103 63.65,80.664 63.65,80.123 62.95,79.423 62.95,78.77
NetL6_1 on Top Layer "NetL6_1" (solid, pour order 138): 64.875,73.863 65.338,73.4 66.6,73.4 66.6,71.1 66.598,71.098 65.301,71.098 65.301,72.722 64.875,73.148
GND on Signal Layer 1 "GND_L02" (solid, remove dead copper, pour order 99): -1,138 172,138 172,-1 -1,-1

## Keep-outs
Keep-Out Layer:
  lines w0.1: 133.661,133.38 142.561,133.38 142.561,135.53 133.661,135.53 133.661,133.38

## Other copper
Top Layer:
  rectangle net VDD2_DDR: 47.155,73.8 50.125,75.6
  text "1" at 134.025,133.812 h2
Signal Layer 1:
  text "2" at 135.312,133.812 h2
Signal Layer 2:
  text "5" at 140.661,133.834 h2
Bottom Layer:
  text "6" at 142.159,133.823 h2

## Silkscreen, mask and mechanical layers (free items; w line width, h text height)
Top Overlay:
  text "VBAT" at 63.016,59.792 h1.2
Top Solder:
  region: 133.736,135.455 133.736,133.455 142.486,133.455 142.486,135.455
Bottom Solder:
  region: 133.736,135.455 133.736,133.455 142.486,133.455 142.486,135.455
M1-Board Shape:
  lines w0.1: 1,137 ccw(c1,136) 0,136 0,95 0,1 ccw(c1,1) 1,0 171,0 ccw(c171,1) 172,1 172,136 ccw(c171,136) 171,137 ; 1,137 1,137 ; 1,137 171,137 ; 171,137 171,137
M2-Board Dimensions:
  lines w0.1: 1,137 ccw(c1,136) 0,136 0,1 ccw(c1,1) 1,0 171,0 ccw(c171,1) 172,1 172,136 ccw(c171,136) 171,137 ; 1,137 1,137 ; 1,137 171,137 ; 171,137 171,137
Drill Drawing:
  drawing of 183 lines, arcs and shapes, not listed
  text "PCB SPECIFICATIONS :" at 3.455,183.85 h3
  text "MINIMUN PARAMETERS" at 155.325,183.145 h3
  text "PCB : TYPE 3" at 194.663,183.121 h3
  text "A.   MATERIAL :" at 3.455,179.85 h3
  text "FR-4" at 41.955,179.85 h3
  text "TG-170" at 58.455,179.85 h3
  text "X  TG-150" at 76.705,179.85 h3
  text "TG-140" at 92.705,179.85 h3
  text "DEFAULT" at 155.325,177.645 h3
  text "ASPECT-RATIO, AXE Z :" at 194.663,177.621 h3
  text "B.   MATERIAL FAMILY :" at 3.455,176.85 h3
  text "N/A" at 41.955,176.85 h3
  text "C.   SOLDERMASK COLOR :" at 3.455,173.85 h3
  text "GREEN" at 41.955,173.85 h3
  text "X  BLUE" at 58.455,173.85 h3
  text "RED" at 76.705,173.85 h3
  text "BLACK" at 92.705,173.85 h3
  text "TRACKS : 0.100mm           / GAPS : 0.100mm" at 155.325,171.895 h3
  text "6 :1  to  8 :1 / LEVEL \"B\"" at 194.682,170.874 h3
  text "D.   SILKSCREEN COLOR :" at 3.455,170.85 h3
  text "X  WHITE" at 41.955,170.85 h3
  text "YELLOW" at 58.455,170.85 h3
  text "BLACK" at 76.705,170.85 h3
  text "E.   SURFACE FINISH :" at 3.455,167.85 h3
  text "X  ENIG" at 41.955,167.85 h3
  text "IMMERSION SILVER" at 58.455,167.85 h3
  text "IMMERSION TIN" at 92.705,167.85 h3
  text "BGA :" at 155.3,167.07 h3
  text "Layer" at 244.479,166.45 h2
  text "Name" at 252.843,166.45 h2
  text "Material" at 269.012,166.45 h2
  text "Thickness" at 283.545,166.45 h2
  text "Constant" at 295.481,166.45 h2
  text "HASL" at 41.955,164.85 h3
  text "HASL (PB-FREE)" at 58.455,164.85 h3
  text "GOLDEN FINGER" at 92.705,164.85 h3
  text "Top Overlay" at 252.843,162.45 h2
  text "F.   IMPEDANCE CONTROL :" at 3.455,161.85 h3
  text "NO" at 41.955,161.85 h3
  text "X  YES" at 58.455,161.85 h3
  text "TRACKS : 0.090mm           / GAPS : 0.090mm" at 155.3,161.32 h3
  text "G.   THROUGH VIA :" at 3.455,158.85 h3
  text "PLUG THE VIAS WHICH ARE COVERED WITH SOLDERMASK ONE OR TWO SIDE." at 41.955,158.85 h3
  text "Top Solder" at 252.843,158.45 h2
  text "Solder Resist" at 269.012,158.45 h2
  text "0.025mm" at 283.545,158.45 h2
  text "3.5" at 295.481,158.45 h2
  text "PLUG MATERIAL :" at 41.955,155.85 h3
  text "X  SOLDERMASK" at 67.455,155.85 h3
  text "NON-CONDUCTIVE EPOXY." at 92.705,155.85 h3
  text "1" at 244.479,154.45 h2
  text "Top Layer" at 252.843,154.45 h2
  text "0.037mm" at 283.545,154.45 h2
  text "H.   STACK-UP :" at 3.455,152.85 h3
  text "SEE LAYER STACK-UP SEQUENCE FOR OVERALL THICKNESS." at 41.955,152.85 h3
  text "Dielectric 1" at 252.843,150.45 h2
  text "0.070mm" at 283.545,150.45 h2
  text "3.8" at 295.481,150.45 h2
  text "2" at 244.478,146.45 h2
  text "Signal Layer 1" at 252.843,146.45 h2
  text "0.035mm" at 283.545,146.45 h2
  text "Dielectric 2" at 252.843,142.45 h2
  text "1.330mm" at 283.545,142.45 h2
  text "4.3" at 295.481,142.45 h2
  text "3" at 244.479,138.45 h2
  text "Signal Layer 2" at 252.843,138.45 h2
  text "0.035mm" at 283.545,138.45 h2
  text "Dielectric 3" at 252.843,134.45 h2
  text "0.070mm" at 283.545,134.45 h2
  text "3.8" at 295.481,134.45 h2
  text "4" at 244.479,130.45 h2
  text "Bottom Layer" at 252.843,130.45 h2
  text "0.037mm" at 283.545,130.45 h2
  text "Bottom Solder" at 252.843,126.45 h2
  text "Solder Resist" at 269.012,126.45 h2
  text "0.025mm" at 283.545,126.45 h2
  text "3.5" at 295.481,126.45 h2
  text "Bottom Overlay" at 252.843,122.45 h2
  text "Symbol" at 183.641,20.279 h2.4
  text "Count" at 193.03,20.279 h2.4
  text "Hole Size" at 202.766,20.279 h2.4
  text "Plated" at 221,20.279 h2.4
  text "Hole Type" at 229.244,20.279 h2.4
  text "Drill Layer Pair" at 241.243,20.279 h2.4
  text "Via/Pad" at 263.972,20.279 h2.4
  text "Pad Shape" at 273.804,20.279 h2.4
  text "Hole Length" at 286.649,20.279 h2.4
  text "448" at 193.03,16.141 h2
  text "0.200mm (7.87mil)" at 202.766,16.141 h2
  text "PTH" at 221,16.141 h2
  text "Round" at 229.244,16.141 h2
  text "Top Layer - Bottom Layer" at 241.243,16.141 h2
  text "Via" at 263.972,16.141 h2
  text "Rounded" at 273.804,16.141 h2
  text "-" at 286.649,16.141 h2
  text "D" at 182.854,15.888 h1.84
  text "3" at 193.03,12.004 h2
  text "0.250mm (9.84mil)" at 202.766,12.004 h2
  text "PTH" at 221,12.004 h2
  text "Round" at 229.244,12.004 h2
  text "Top Layer - Bottom Layer" at 241.243,12.004 h2
  text "Via" at 263.972,12.004 h2
  text "Rounded" at 273.804,12.004 h2
  text "-" at 286.649,12.004 h2
  text "E" at 182.854,11.75 h1.84
  text "387" at 193.03,7.867 h2
  text "0.350mm (13.78mil)" at 202.766,7.867 h2
  text "PTH" at 221,7.867 h2
  text "Round" at 229.244,7.867 h2
  text "Top Layer - Bottom Layer" at 241.243,7.867 h2
  text "Via" at 263.972,7.867 h2
  text "Rounded" at 273.804,7.867 h2
  text "-" at 286.649,7.867 h2
  text "F" at 182.854,7.613 h1.84
  text "2" at 193.03,3.729 h2
  text "0.500mm (19.69mil)" at 202.766,3.729 h2
  text "PTH" at 221,3.729 h2
  text "Round" at 229.244,3.729 h2
  text "Top Layer - Bottom Layer" at 241.243,3.729 h2
  text "Pad" at 263.972,3.729 h2
  text "Rounded" at 273.804,3.729 h2
  text "-" at 286.649,3.729 h2
  text "840 Total" at 193.03,-0.408 h2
